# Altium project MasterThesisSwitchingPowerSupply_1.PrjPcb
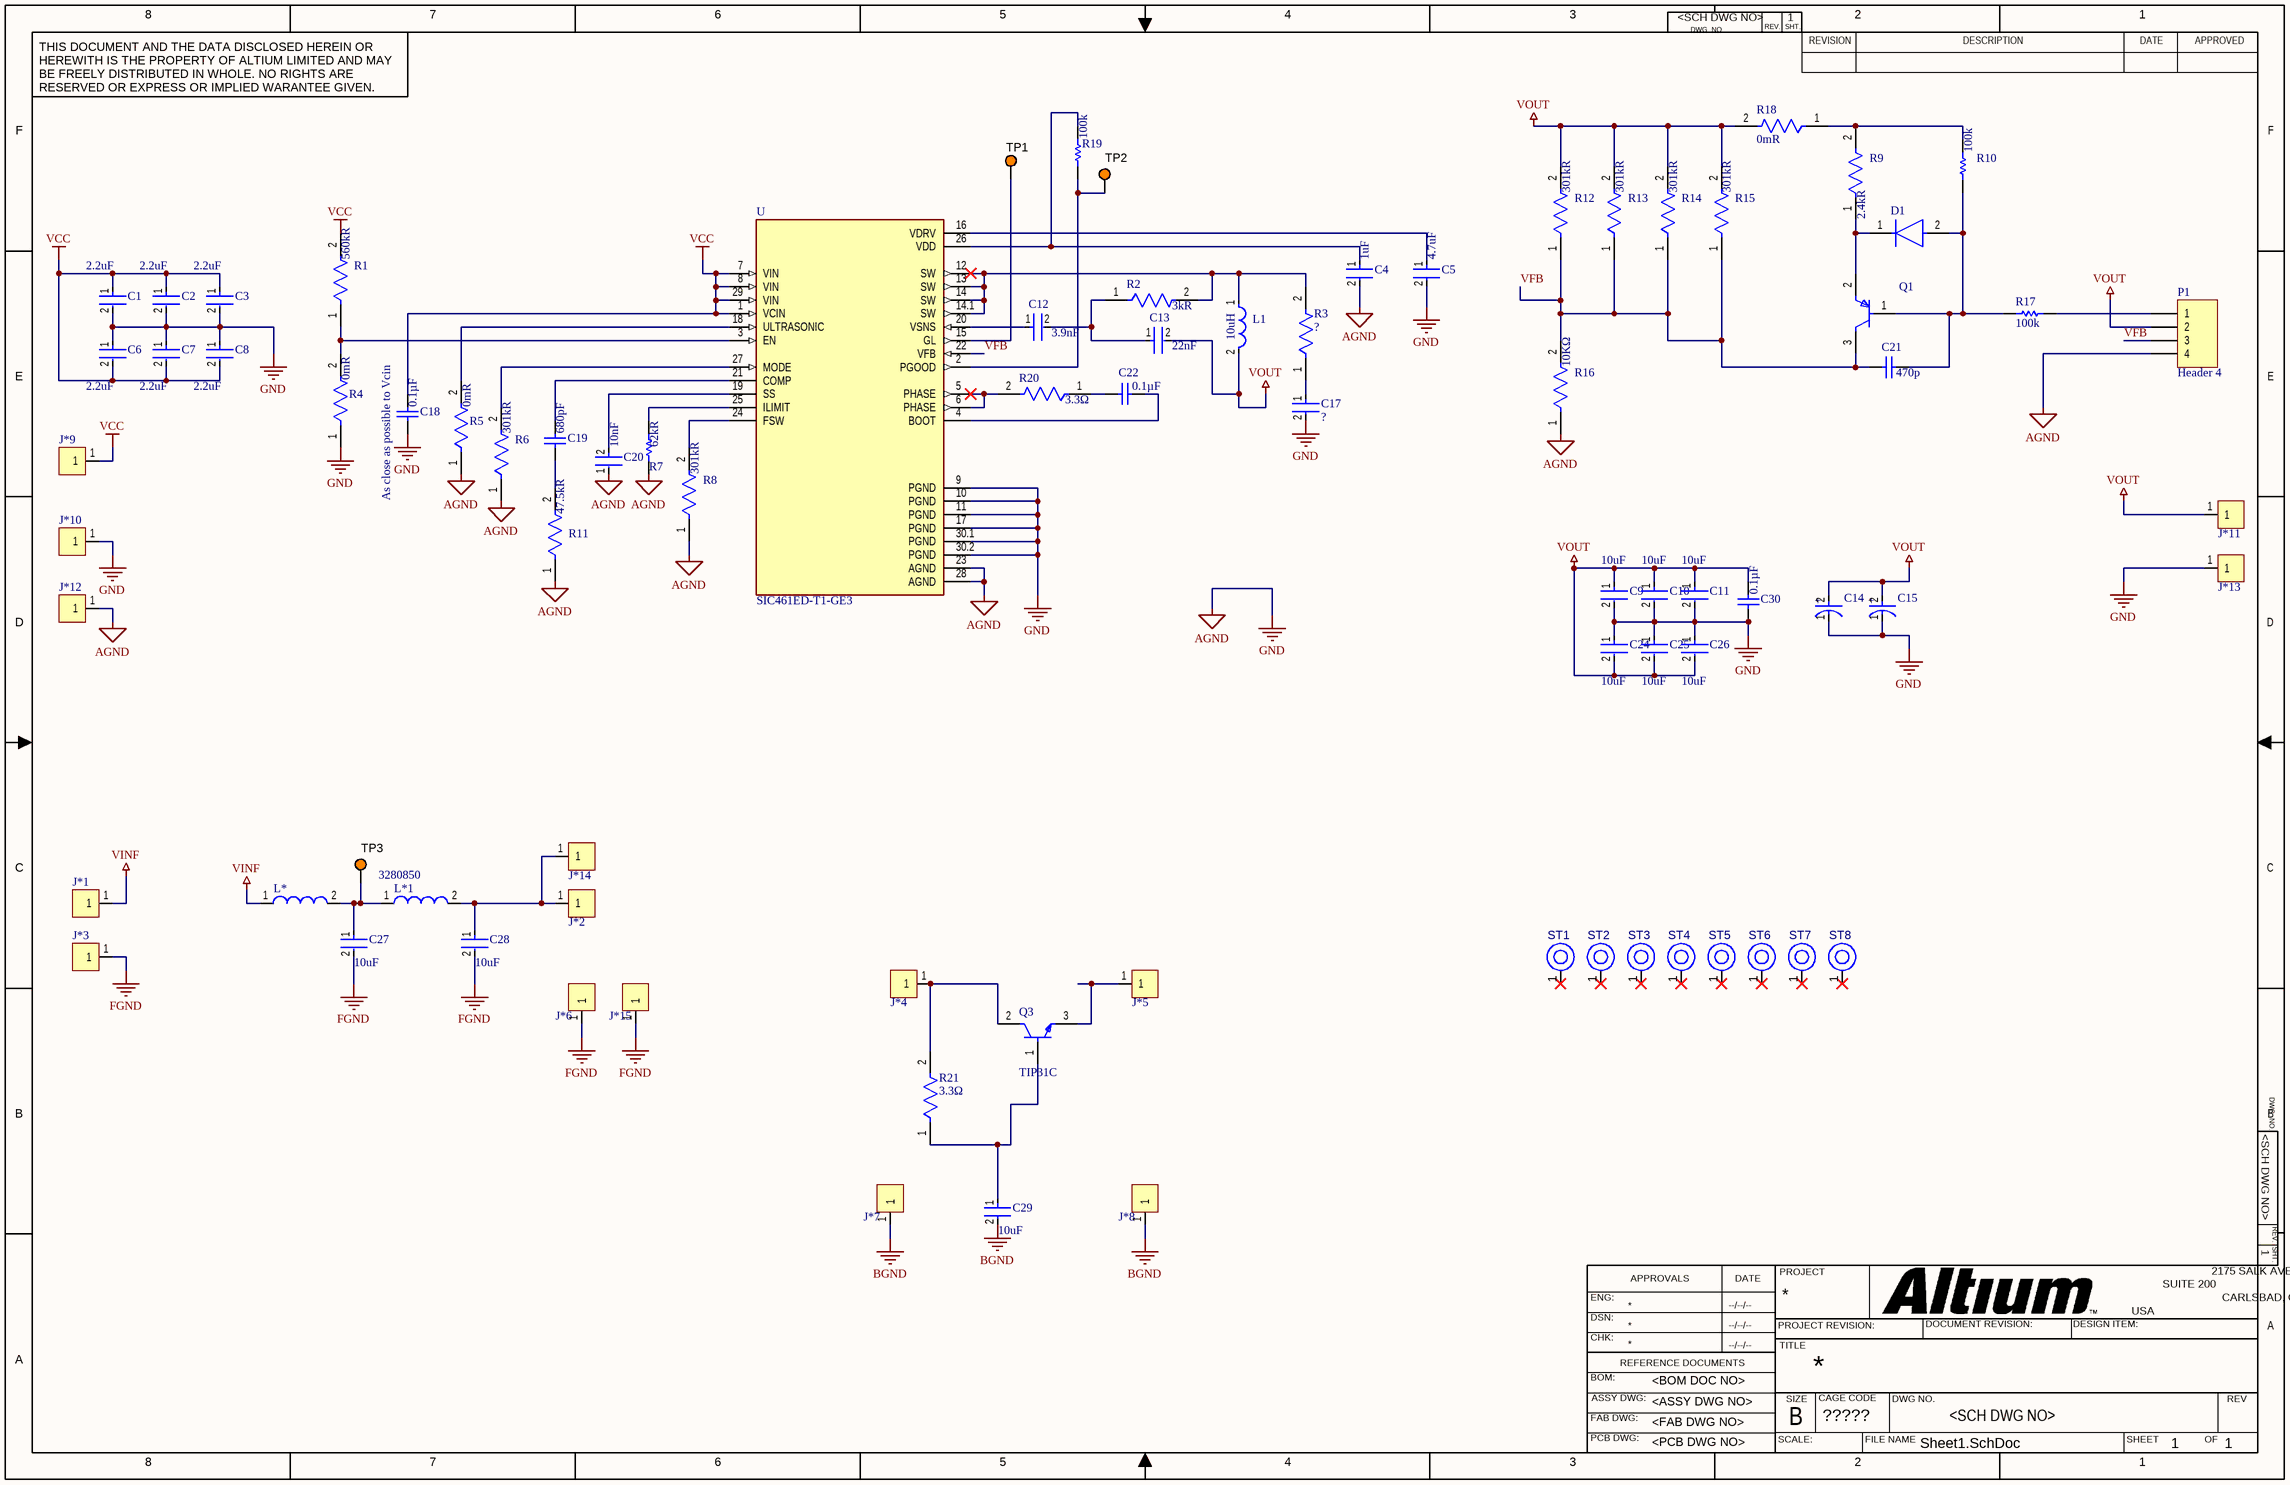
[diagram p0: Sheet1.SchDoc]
CAGE_CODE: ?????; CONTRACT_NUMBER: <CONTRACT NO>; DOC_NO_ASSY_DWG: <ASSY DWG NO>; DOC_NO_BOM: <BOM DOC NO>; DOC_NO_FAB_DWG: <FAB DWG NO>; DOC_NO_SCH_DWG: <SCH DWG NO>; PCB_2_DEC_TOL: +/-.01; PCB_3_DEC_TOL: +/-.010; PCB_ANG_TOL: +/-1/2; PCB_ASSEMBLY_NO: <PCB ASSY NO>; PCB_CHECKER: - -----; PCB_CHECKER_APP_DATE: --/--/----; PCB_DESIGNER: - -----; PCB_DESIGNER_APP_DATE: --/--/----; PCB_DWG_NO: <PCB DWG NO>; PCB_ENGINEER: - -----; PCB_ENGINEER_APP_DATE: --/--/----; PCB_PART_NUMBER: <PCB PN>; PCB_REV: A; SCH_REV: A
1 sheet, 83 parts. Net scope: global (net labels, ports and power ports of the same name join across sheets).
Board file: PCB1.PcbDoc

## Sheet Sheet1.SchDoc
size 431 x 279 mm; SheetNumber: 1; SheetTotal: 1; ENG_APP_DATE: --/--/--; DSN_APP_DATE: --/--/--; CHK_APP_DATE: --/--/--

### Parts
C1  Capacitance: 2.2uF  [FP-CL31-IPC_B]  (hidden comment: CL31B225KBHNNNF)
C2  Capacitance: 2.2uF  [FP-CL31-IPC_B]  (hidden comment: CL31B225KBHNNNF)
C3  Capacitance: 2.2uF  [FP-CL31-IPC_B]  (hidden comment: CL31B225KBHNNNF)
C4  Capacitance: 1uF  [FP-0603-L_1_6_0_15-W_0_8-IPC_C]  (hidden comment: UMK107AB7105KA-T)
C5  Capacitance: 4.7uF  [FP-0805-L_2_0_0_15-W_1_25-IPC_C]  (hidden comment: TMK212AB7475KG-T)
C6  Capacitance: 2.2uF  [FP-CL31-IPC_B]  (hidden comment: CL31B225KBHNNNF)
C7  Capacitance: 2.2uF  [FP-CL31-IPC_B]  (hidden comment: CL31B225KBHNNNF)
C8  Capacitance: 2.2uF  [FP-CL31-IPC_B]  (hidden comment: CL31B225KBHNNNF)
C9  value 10uF  [FP-CL31B106KBHNNNE-MFG]  (hidden comment: CL31B106KBHNNNE)
C10  value 10uF  [FP-CL31B106KBHNNNE-MFG]  (hidden comment: CL31B106KBHNNNE)
C11  value 10uF  [FP-CL31B106KBHNNNE-MFG]  (hidden comment: CL31B106KBHNNNE)
C12  Capacitance: 3.9nF  [FP-CL21-IPC_B]  (hidden comment: CL21B392KBANNNC)
C13  Capacitance: 22nF  [FP-CL21-IPC_C]  (hidden comment: CL21B223KBANNWC)
C14  EEEFP1V331AP  [FP-FPG-MFG]  (value not drawn)
C15  EEEFP1V331AP  [FP-FPG-MFG]  (value not drawn)
C17  UMK107AB7105KA-T  [FP-0603-L_1_6_0_15-W_0_8-IPC_C]  (value not drawn)
C18  Capacitance: 0.1µF  [SAMS-C0603-2_L]  (hidden comment: CL10B104KB8NNNC)
C19  value 680pF  [CAPC0603(1608)100_L]  (hidden comment: CAP 680pF 50V 0603(1608))
C20  Capacitance: 10nF  [FP-C1608-080-0_1-MFG]  (hidden comment: C1608X7R1H103M080AA)
C21  value 470p  [CAPC1608X90X35LL15T15]  (hidden comment: 06035C471K4T2A)
C22  Capacitance: 0.1µF  [SAMS-C0603-2_L]  (hidden comment: CL10B104KB8NNNC)
C24  value 10uF  [FP-CL31B106KBHNNNE-MFG]  (hidden comment: CL31B106KBHNNNE)
C25  value 10uF  [FP-CL31B106KBHNNNE-MFG]  (hidden comment: CL31B106KBHNNNE)
C26  value 10uF  [FP-CL31B106KBHNNNE-MFG]  (hidden comment: CL31B106KBHNNNE)
C27  value 10uF  [FP-CL31B106KBHNNNE-MFG]  (hidden comment: CL31B106KBHNNNE)
C28  value 10uF  [FP-CL31B106KBHNNNE-MFG]  (hidden comment: CL31B106KBHNNNE)
C29  value 10uF  [FP-CL31B106KBHNNNE-MFG]  (hidden comment: CL31B106KBHNNNE)
C30  Capacitance: 0.1µF  [SAMS-C0603-2_L]  (hidden comment: CL10B104KB8NNNC)
D1  BAS316,115  [FP-SOD323-IPC_A]  (value not drawn)
J*1  Conn_5x5mm  [Conn_5x5mm]  (value not drawn)
J*2  Conn_5x5mm  [Conn_5x5mm]  (value not drawn)
J*3  Conn_5x5mm  [Conn_5x5mm]  (value not drawn)
J*4  Conn_5x5mm  [Conn_5x5mm]  (value not drawn)
J*5  Conn_5x5mm  [Conn_5x5mm]  (value not drawn)
J*6  Conn_5x5mm  [Conn_5x5mm]  (value not drawn)
J*7  Conn_5x5mm  [Conn_5x5mm]  (value not drawn)
J*8  Conn_5x5mm  [Conn_5x5mm]  (value not drawn)
J*9  Conn_5x5mm  [Conn_5x5mm]  (value not drawn)
J*10  Conn_5x5mm  [Conn_5x5mm]  (value not drawn)
J*11  Conn_5x5mm  [Conn_5x5mm]  (value not drawn)
J*12  Conn_5x5mm  [Conn_5x5mm]  (value not drawn)
J*13  Conn_5x5mm  [Conn_5x5mm]  (value not drawn)
J*14  Conn_5x5mm  [Conn_5x5mm]  (value not drawn)
J*15  Conn_5x5mm  [Conn_5x5mm]  (value not drawn)
L1  Inductance: 10uH  [FP-IHLP-6767GZ-FP_3_825x1-MFG]  (hidden comment: IHLP6767GZER100M01)
L*  L  [Inductance_SRP1038C-3R3M]  (value not drawn)
L*1  Supplier Part Number 1: 3280850  [Inductance_SRP1038C-3R3M]  (hidden comment: L)
P1  Header 4  [HDR1X4]
Q1  MMBT5401-7-F  [FP-SOT23-MFG]  (value not drawn)
Q3  TIP31C  [FP-TO-220-P0A0015988-MFG]
R1  Resistance: 560kR  [FP-AC0603-IPC_C]  (hidden comment: AC0603FR-07560KL)
R2  Resistance: 3kR  [FP-CRCW0805-e3-IPC_C]  (hidden comment: CRCW08053K00FKEA)
R3  CRG0603ZR  [FP-CRG0603-IPC_C]  (value not drawn)
R4  Resistance: 0mR  [FP-CRG0603-IPC_C]  (hidden comment: CRG0603ZR)
R5  Resistance: 0mR  [FP-CRG0603-IPC_C]  (hidden comment: CRG0603ZR)
R6  Resistance: 301kR  [FP-CRCW0603-e3-IPC_C]  (hidden comment: CRCW0603301KFKEA)
R7  Resistance: 62kR  [RESC1608X55X25LL10T15]  (hidden comment: RC0603FR-0762KL)
R8  Resistance: 301kR  [FP-CRCW0603-e3-IPC_C]  (hidden comment: CRCW0603301KFKEA)
R9  Resistance: 2.4kR  [FP-AC0603-IPC_B]  (hidden comment: AC0603FR-072K4L)
R10  value 100k  [RESC1608X55X30LL15T15]  (hidden comment: ERJ-3EKF1003V)
R11  Resistance: 47.5kR  [FP-AC0603-MFG]  (hidden comment: AC0603FR-0747K5L)
R12  Resistance: 301kR  [FP-CRCW0603-e3-IPC_C]  (hidden comment: CRCW0603301KFKEA)
R13  Resistance: 301kR  [FP-CRCW0603-e3-IPC_C]  (hidden comment: CRCW0603301KFKEA)
R14  Resistance: 301kR  [FP-CRCW0603-e3-IPC_C]  (hidden comment: CRCW0603301KFKEA)
R15  Resistance: 301kR  [FP-CRCW0603-e3-IPC_C]  (hidden comment: CRCW0603301KFKEA)
R16  value 10KΩ  [FP-RT0603-IPC_B]  (hidden comment: RT0603FRE0710KL)
R17  value 100k  [RESC1608X55X30LL15T15]  (hidden comment: ERJ-3EKF1003V)
R18  Resistance: 0mR  [FP-CRG0603-IPC_C]  (hidden comment: CRG0603ZR)
R19  value 100k  [RESC1608X55X30LL15T15]  (hidden comment: ERJ-3EKF1003V)
R20  value 3.3Ω  [FP-RT0603-IPC_B]  (hidden comment: RT0603FRE073R3L)
R21  Resistance: 3.3Ω  [FP-RT1206-MFG]  (hidden comment: RT1206FRE073R3L)
ST1  PTH-M2D5X5  [PTH-M2D5X5]  (value not drawn)
ST2  PTH-M2D5X5  [PTH-M2D5X5]  (value not drawn)
ST3  PTH-M2D5X5  [PTH-M2D5X5]  (value not drawn)
ST4  PTH-M2D5X5  [PTH-M2D5X5]  (value not drawn)
ST5  PTH-M2D5X5  [PTH-M2D5X5]  (value not drawn)
ST6  PTH-M2D5X5  [PTH-M2D5X5]  (value not drawn)
ST7  PTH-M2D5X5  [PTH-M2D5X5]  (value not drawn)
ST8  PTH-M2D5X5  [PTH-M2D5X5]  (value not drawn)
TP1  5003  [KSTN-5003]  (value not drawn)
TP2  5003  [KSTN-5003]  (value not drawn)
TP3  5003  [KSTN-5003]  (value not drawn)
U  SIC461ED-T1-GE3  [CONV_SIC461ED-T1-GE3]

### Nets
AGND: C1.2 C2.2 C3.2 C4.2 C5.2 C6.1 C7.1 C8.1 C9.2 C10.2 C11.2 C14.1(C) C15.1(C) C17.2 C18.1 C20.1 C24.1 C25.1 C26.1 C30.1 J*10.1 J*12.1 J*13.1 P1.4 R4.1 R5.1 R6.1 R7.1 R8.1 R11.1 R16.1 U.9(PGND) U.10(PGND) U.11(PGND) U.17(PGND) U.23(AGND) U.28(AGND) U.30.1(PGND) U.30.2(PGND)  [also labelled GND]
BGND: C29.2 J*7.1 J*8.1
FGND: C27.2 C28.2 J*3.1 J*6.1 J*15.1
VCC: C1.1 C2.1 C3.1 C6.2 C7.2 C8.2 C18.2 J*9.1 R1.2 U.1(VCIN) U.7(VIN) U.8(VIN) U.29(VIN)
VINF: J*1.1 L*.1
VOUT: C9.1 C10.1 C11.1 C13.2 C14.2(A) C15.2(A) C24.2 C25.2 C26.2 C30.2 J*11.1 L1.2 P1.2 R12.2 R13.2 R14.2 R15.2 R18.2
VFB: C21.1 P1.3 Q1.3(C) R12.1 R13.1 R14.1 R15.1 R16.2 U.22(VFB)
NetC4_1: C4.1 R19.2 U.26(VDD)
NetC5_1: C5.1 U.16(VDRV)
NetC12_1: C12.1 U.20(VSNS)
NetC12_2: C12.2 C13.1 R2.1
NetC17_1: C17.1 R3.1
NetC19_1: C19.1 R11.2
NetC19_2: C19.2 U.21(COMP)
NetC20_2: C20.2 U.19(SS)
NetC21_2: C21.2 D1.2(A) Q1.1(B) R10.1 R17.2
NetC22_1: C22.1 U.4(BOOT)
NetC22_2: C22.2 R20.1
NetC27_1: C27.1 L*.2 L*1.1 TP3.1
NetC28_1: C28.1 J*2.1 J*14.1 L*1.2
NetC29_1: C29.1 Q3.1(B) R21.1
NetD1_1: D1.1(C) Q1.2(E) R9.1
NetJ*4_1: J*4.1 Q3.2(C) R21.2
NetJ*5_1: J*5.1 Q3.3(E)
NetL1_1: L1.1 R2.2 R3.2 U.12(SW) U.13(SW) U.14(SW) U.14.1(SW)
NetP1_1: P1.1 R17.1
NetR1_1: R1.1 R4.2 U.3(EN)
NetR5_2: R5.2 U.18(ULTRASONIC)
NetR6_2: R6.2 U.27(MODE)
NetR7_2: R7.2 U.25(ILIMIT)
NetR8_2: R8.2 U.24(FSW)
NetR9_2: R9.2 R10.2 R18.1
NetR19_1: R19.1 TP2.1 U.2(PGOOD)
NetR20_2: R20.2 U.5(PHASE) U.6(PHASE)
NetTP1_1: TP1.1 U.15(GL)

Not connected (* = marked no-connect by the designer): ST1 1(H1)*; ST2 1(H1)*; ST3 1(H1)*; ST4 1(H1)*; ST5 1(H1)*; ST6 1(H1)*; ST7 1(H1)*; ST8 1(H1)*

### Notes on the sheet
- (near C18) As close as possible to Vcin

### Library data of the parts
C1-C3 C6-C8 = CMP-13271-000591-1: Cap Ceramic 2.2uF 50V X7R ±10% SMD 1206 +125°C Embossed T/R
C4 C17 = CMP-2000-07531-4: Ceramic Capacitor General Use 1uF ±10% 50V X7R 0603
C5 = CMP-14477-004132-2: Multilayer Ceramic Capacitor 4.7 uF 25V X7R 10% SMD 0805 T/R
C9-C11 C24-C29 = CMP-2000-07530-2: CAP CER 10UF 50V X7R 1206; Manufacturer: Samsung; Tolerance: 10%; Material: Ceramic; Temperature Coefficient: 15%
C12 = CMP-13271-000410-1: CL21 Series 0805 3.9nF 50V ±10% Tolerance X7R Multilayer Ceramic Chip Capacitor
C13 = CMP-13271-002873-1: CL21 Series 0805 22nF 50V ±10% Tolerance X7R Multilayer Ceramic Chip Capacitor
C14 C15 = CMP-05427-000057-1: CAP ALUM 330UF 20% 35V SMD; Material: Aluminium; ESR (Equivalent Series Resistance): 60mR; Life (Hours): 2000Hour; Ripple Current (AC): 1.19A; Leakage Current: 115.5uA; Polarity: Polar
C18 C22 C30 = CMP-2000-05332-1: Multi-layer Ceramic Capacitor, -55 to 125 degC, 2-Pin SMD (0603), RoHS, Tape and Reel; Manufacturer: Samsung Electro-Mechanics; Rated Voltage: 50V; Dielectric: X7R; Tolerance (%): ±10%
C19 = CMP-1035-01782-1: CAP 680pF 50V ±5% 0603 (1608 Metric) Thickness 1mm SMD; Tolerance: Â±5%; Case-EIA: 0603; Case-Metric: 1608
C20 = CMP-08246-006703-1: Multilayer Ceramic Capacitors 10nF ±20% 50V X7R SMD 0603
C21 = CMP-2006-02099-1: Manufacturer: AVX Interconnect / Elco
D1 = CMP-14399-000012-1: DIODE GEN PURP 100V 250MA SOD323
L1 = CMP-02424-000414-1: Commercial Inductors, High Saturation Series 10uH 16.5A 12mΩ 20%; Saturation Current: 25A; Shielding: Shielded; Core Material: Metal; DC Resistance (DCR): 12mR; Test Frequency: 100kHz; Self Resonant Frequency: 2MHz
L* L*1 = Inductance_SRP1038C-3R3M: SRP1038C-3R3M 3.3 uH; 11.8 mOhms; 14 A
P1 = Header 4: Header, 4-Pin
Q1 = CMP-12798-000015-1: TRANS PNP 150V 0.6A SMD SOT23-3; Manufacturer: Diodes Inc.; Max Collector Current: -600mA; Standoff Height: 0.013mm; Collector Base Voltage: -160V; Rthja Max: 403°C/W; Max Junction Temp: +150°C; Hfe Testvce: -5V; Number Of Pnp: 1; Collector Emitter Saturation Voltage: -0.5V; Collector Emitter Breakdown Voltage: -150V; Power Dissipation: 310mW; Hfe Testic: -10mA; Automotive Grade: Grade 0; Hfe Min: 60; Hfe Max: 240; Gain Bandwidth Product: 300MHz
Q3 = CMP-12195-000001-1: TRANS NPN 100V 3A TO-220; Manufacturer: STMicroelectronics; Hfe Max: 50; Number Of Npn: 1; Max Junction Temp: +150°C; Standoff Height: 3.5mm; Emitter Base Voltage: 5V; Collector Emitter Saturation Voltage: 1.2V; Power Dissipation: 2W; Hfe Testvce: 4V; Hfe Min: 10
R1 = CMP-03412-028160-2: RES 560KΩ 1.00% 0.1W 0603; Voltage Rating: 50V; Temperature Coefficient: 100ppm/°C; Tolerance: 1%; Max Power Dissipation: 100mW
R2 = CMP-2001-03869-2: RES Thick Film, 3kΩ, 1%, 0.125W, 100ppm/°C, 0805; Power Rating: 125mW; Working Voltage: 150V
R3-R5 R18 = CMP-03211-011415-1: RES SMD 0 OHM JUMPER 1/10W 0603; Voltage Rating: 50V; Power Rating: 100mW; Number of Resistors: 1; Tolerance: 0%; Temperature Coefficient: 100ppm/°C
R6 R8 R12-R15 = CMP-2000-03218-2: RES Thick Film, 301kΩ, 1%, 0.1W, 100ppm/°C, 0603; Voltage Rating: 75V; Max Power Dissipation: 100mW
R7 = CMP-2000-04104-1: Manufacturer: Yageo
R9 = CMP-03412-003336-2: RES 2.4KΩ 1.00% 0.1W 0603; Temperature Coefficient: 100ppm/°C; Tolerance: 1%; Max Power Dissipation: 100mW; Voltage Rating: 50V
R10 R17 R19 = CMP-2000-00182-1: Manufacturer: Panasonic
R11 = CMP-03412-027829-2: RES 47.5KΩ 1.00% 0.1W 0603; Tolerance: 1%; Temperature Coefficient: 100ppm/°C; Voltage Rating: 50V; Power Rating: 100mW
R16 = CMP-03412-005349-1: RES SMD 10K OHM 1% 1/10W 0603; Manufacturer: Yageo; Temperature Coefficient: 50 ppm/°C; Power Rating: 0.1W; Tolerance: 0.01; Voltage Rating: 75V
R20 = CMP-03412-003867-1: RES SMD 3.3 OHM 1% 1/10W 0603; Manufacturer: Yageo; Power Rating: 0.1W; Temperature Coefficient: 50 ppm/°C; Voltage Rating: 75V; Tolerance: 0.01
R21 = CMP-03412-007399-1: RT1206 3.3Ω 0.25W 50 ppm/°C 0.02%; Manufacturer: Yageo; Voltage Rating: 200V; Tolerance: 0.0002
ST1-ST8 = CMP-00028-00004-1: M2 PTH (2.5mm), 5mm pad
TP1-TP3 = CMP-002-00037-1: Test Point, Orange, Height 4.6 mm, Tail Length 3 mm, 1-Pin THD, RoHS; Manufacturer: Keystone
U = SIC461ED-T1-GE3: Buck Switching Regulator IC Positive Adjustable 0.8V 1 Output 10A PowerPAKÂ® MLP55-27; MF: Vishay Siliconix

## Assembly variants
Variant of MasterThesisSwitchingPowerSupply_1: not fitted C? Q? R13 R14 R15 R? R? R?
